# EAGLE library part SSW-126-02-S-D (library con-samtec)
THROUGH-HOLE .025" SQ POST SOCKET Source: Samtec SSW.pdf
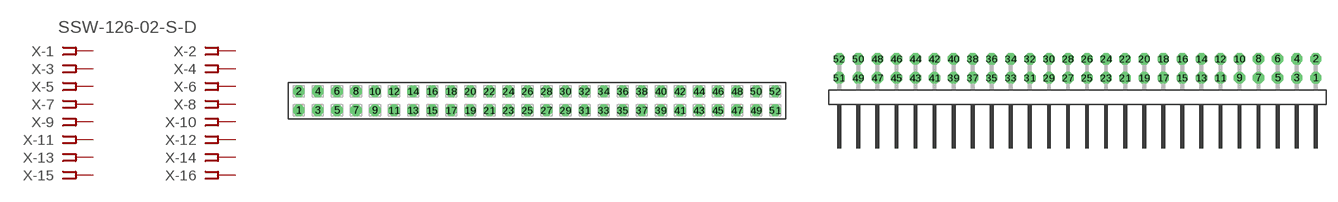
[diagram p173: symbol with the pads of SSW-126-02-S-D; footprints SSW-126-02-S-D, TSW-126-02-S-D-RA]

Designator prefix X; gates -1=FPINV -2=FPIN -3=FPIN -4=FPIN -5=FPIN -6=FPIN -7=FPIN -8=FPIN -9=FPIN -10=FPIN -11=FPIN -12=FPIN -13=FPIN -14=FPIN -15=FPIN -16=FPIN -17=FPIN -18=FPIN -19=FPIN -20=FPIN -21=FPIN -22=FPIN -23=FPIN -24=FPIN -25=FPIN -26=FPIN -27=FPIN -28=FPIN -29=FPIN -30=FPIN -31=FPIN -32=FPIN -33=FPIN -34=FPIN -35=FPIN -36=FPIN -37=FPIN -38=FPIN -39=FPIN -40=FPIN -41=FPIN -42=FPIN -43=FPIN -44=FPIN -45=FPIN -46=FPIN -47=FPIN -48=FPIN -49=FPIN -50=FPIN -51=FPIN -52=FPIN

## SSW-126-02-S-D (MPN: SSW-126-02-S-D; OC_FARNELL: unknown; OC_NEWARK: 11P9740)  [SSW-126-02-S-D]
1  -1:1  pas
2  -2:1  pas
3  -3:1  pas
4  -4:1  pas
5  -5:1  pas
6  -6:1  pas
7  -7:1  pas
8  -8:1  pas
9  -9:1  pas
10  -10:1  pas
11  -11:1  pas
12  -12:1  pas
13  -13:1  pas
14  -14:1  pas
15  -15:1  pas
16  -16:1  pas
17  -17:1  pas
18  -18:1  pas
19  -19:1  pas
20  -20:1  pas
21  -21:1  pas
22  -22:1  pas
23  -23:1  pas
24  -24:1  pas
25  -25:1  pas
26  -26:1  pas
27  -27:1  pas
28  -28:1  pas
29  -29:1  pas
30  -30:1  pas
31  -31:1  pas
32  -32:1  pas
33  -33:1  pas
34  -34:1  pas
35  -35:1  pas
36  -36:1  pas
37  -37:1  pas
38  -38:1  pas
39  -39:1  pas
40  -40:1  pas
41  -41:1  pas
42  -42:1  pas
43  -43:1  pas
44  -44:1  pas
45  -45:1  pas
46  -46:1  pas
47  -47:1  pas
48  -48:1  pas
49  -49:1  pas
50  -50:1  pas
51  -51:1  pas
52  -52:1  pas

## SSW-126-02-S-D-RA (MPN: SSW-126-02-S-D-RA; OC_FARNELL: unknown; OC_NEWARK: 11P9741)  [TSW-126-02-S-D-RA]
Pads as for SSW-126-02-S-D

## Footprint SSW-126-02-S-D (pad centres in mm)
THROUGH-HOLE .025" SQ POST SOCKET Source: Samtec SSW.pdf
drill 1 pad 1.5 octagon: 1 -31.75,-1.27; 2 -31.75,1.27; 3 -29.21,-1.27; 4 -29.21,1.27; 5 -26.67,-1.27; 6 -26.67,1.27; 7 -24.13,-1.27; 8 -24.13,1.27; 9 -21.59,-1.27; 10 -21.59,1.27; 11 -19.05,-1.27; 12 -19.05,1.27; 13 -16.51,-1.27; 14 -16.51,1.27; 15 -13.97,-1.27; 16 -13.97,1.27; 17 -11.43,-1.27; 18 -11.43,1.27; 19 -8.89,-1.27; 20 -8.89,1.27; 21 -6.35,-1.27; 22 -6.35,1.27; 23 -3.81,-1.27; 24 -3.81,1.27; 25 -1.27,-1.27; 26 -1.27,1.27; 27 1.27,-1.27; 28 1.27,1.27; 29 3.81,-1.27; 30 3.81,1.27; 31 6.35,-1.27; 32 6.35,1.27; 33 8.89,-1.27; 34 8.89,1.27; 35 11.43,-1.27; 36 11.43,1.27; 37 13.97,-1.27; 38 13.97,1.27; 39 16.51,-1.27; 40 16.51,1.27; 41 19.05,-1.27; 42 19.05,1.27; 43 21.59,-1.27; 44 21.59,1.27; 45 24.13,-1.27; 46 24.13,1.27; 47 26.67,-1.27; 48 26.67,1.27; 49 29.21,-1.27; 50 29.21,1.27; 51 31.75,-1.27; 52 31.75,1.27

## Footprint TSW-126-02-S-D-RA (pad centres in mm)
THROUGH-HOLE .025" SQ POST HEADER Source: Samtec TSW.pdf
drill 1 pad 1.5 octagon: 1 31.75,1.524; 2 31.75,4.064; 3 29.21,1.524; 4 29.21,4.064; 5 26.67,1.524; 6 26.67,4.064; 7 24.13,1.524; 8 24.13,4.064; 9 21.59,1.524; 10 21.59,4.064; 11 19.05,1.524; 12 19.05,4.064; 13 16.51,1.524; 14 16.51,4.064; 15 13.97,1.524; 16 13.97,4.064; 17 11.43,1.524; 18 11.43,4.064; 19 8.89,1.524; 20 8.89,4.064; 21 6.35,1.524; 22 6.35,4.064; 23 3.81,1.524; 24 3.81,4.064; 25 1.27,1.524; 26 1.27,4.064; 27 -1.27,1.524; 28 -1.27,4.064; 29 -3.81,1.524; 30 -3.81,4.064; 31 -6.35,1.524; 32 -6.35,4.064; 33 -8.89,1.524; 34 -8.89,4.064; 35 -11.43,1.524; 36 -11.43,4.064; 37 -13.97,1.524; 38 -13.97,4.064; 39 -16.51,1.524; 40 -16.51,4.064; 41 -19.05,1.524; 42 -19.05,4.064; 43 -21.59,1.524; 44 -21.59,4.064; 45 -24.13,1.524; 46 -24.13,4.064; 47 -26.67,1.524; 48 -26.67,4.064; 49 -29.21,1.524; 50 -29.21,4.064; 51 -31.75,1.524; 52 -31.75,4.064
